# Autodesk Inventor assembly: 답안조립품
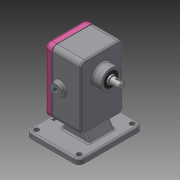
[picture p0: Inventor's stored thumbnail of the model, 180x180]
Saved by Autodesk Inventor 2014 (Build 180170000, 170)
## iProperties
Created: 2020-04
Part Number: 답안조립품
Document SubType Name: Assembly
Designer: kh
Author: kh
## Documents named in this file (11)
- C:\Users\kh\Desktop\700407V1015\답안조립품.iam
- C:\Users\kh\Desktop\700407V1015\본체.ipt
- C:\Users\kh\Desktop\700407V1015\개스킷.ipt
- C:\Users\kh\Desktop\700407V1015\메인축.ipt
- C:\Users\kh\Desktop\700407V1015\베어링부시.ipt
- C:\Users\kh\Desktop\700407V1015\볼트 M5.ipt
- C:\Users\kh\Desktop\700407V1015\서브축.ipt
- C:\Users\kh\Desktop\700407V1015\스퍼기어.ipt
- C:\Users\kh\Desktop\700407V1015\오일 실 16 28 7.ipt
- C:\Users\kh\Desktop\700407V1015\커버.ipt
- C:\Users\kh\Desktop\700407V1015\키 6 x 6 x 18.ipt
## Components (1 placed, 1 different names)
1. 개스킷:1
